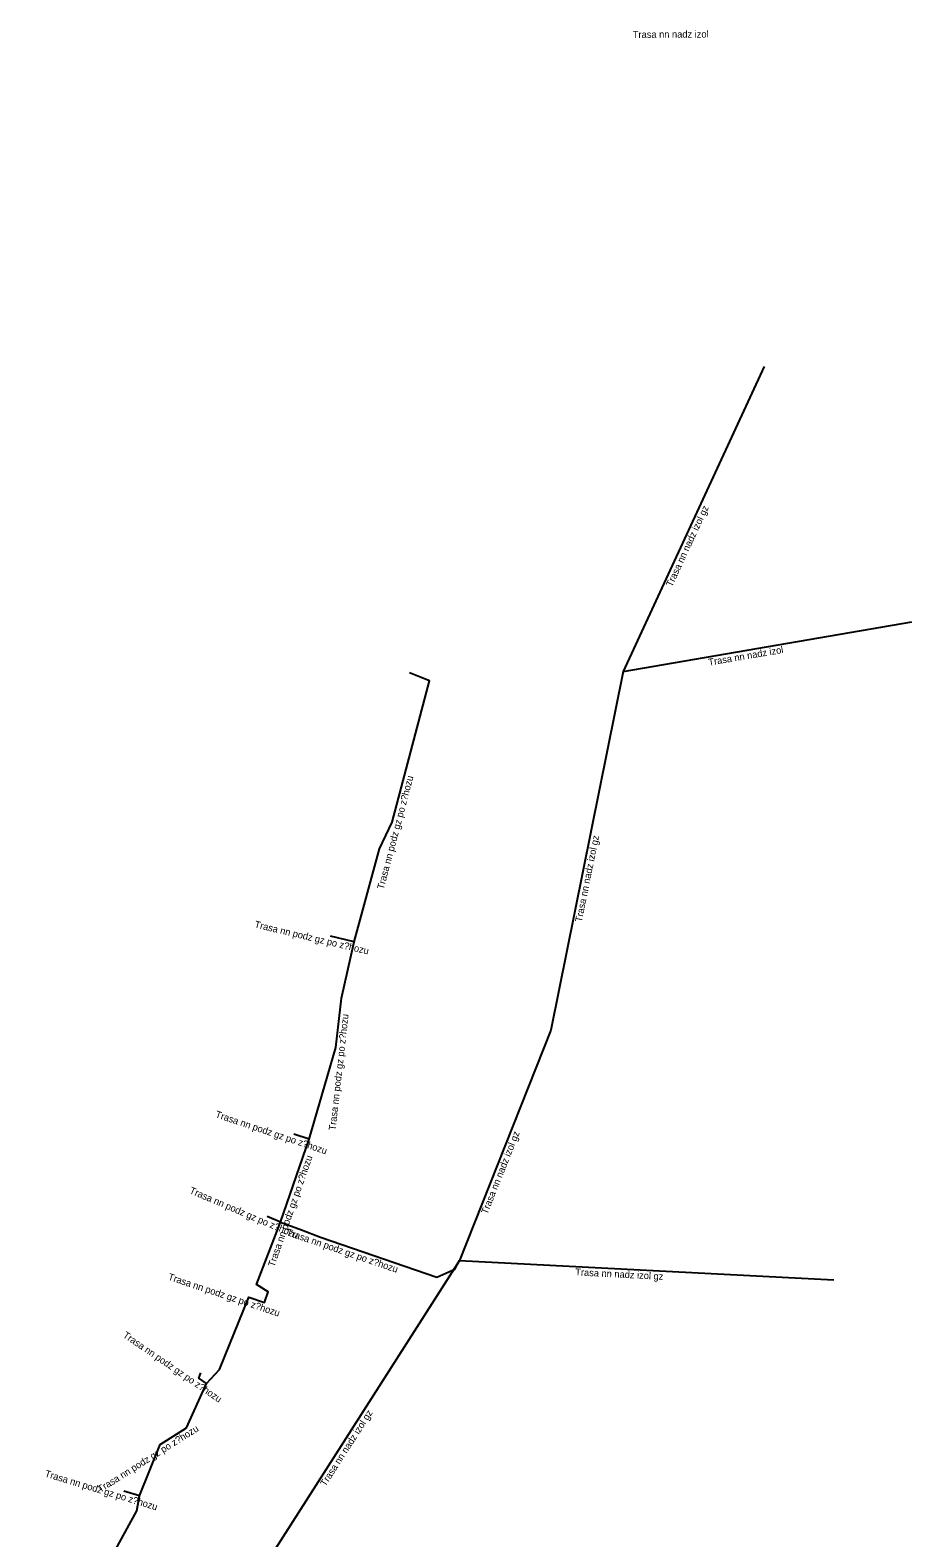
# Model space of a CAD drawing. Extents: x -770668 to -770481, y -1049958 to -1049459.
# Drawn here: x -770567.4 to -770503.8, y -1049855.1 to -1049746.5 of the extents above; entities that cross this region are included whole.
import ezdxf

# ---------------------------------------------------------------- set-up
doc = ezdxf.new("R2010")
doc.units = 0
doc.layers.add('Popiskový text - Ostatní atributy Trasy', color=7, linetype='Continuous')
doc.layers.add('Spojnice NN', color=7, linetype='Continuous')

msp = doc.modelspace()

# ---------------------------------------------------------------- linework, layer by layer
at = {"layer": 'Spojnice NN'}
for points in [[(-770514.47, -1049770.7), (-770524.63, -1049792.67)], [(-770524.63, -1049792.67), (-770503.83, -1049789.09)], [(-770544.02, -1049812.16), (-770542.19, -1049805.45), (-770541.29, -1049803.54), (-770538.6, -1049793.34), (-770540.04, -1049792.78)], [(-770524.63, -1049792.67), (-770529.85, -1049818.52)], [(-770547.27, -1049826.38), (-770545.95, -1049821.84), (-770545.35, -1049819.76), (-770544.95, -1049816.21), (-770544.02, -1049812.16)], [(-770544.02, -1049812.16), (-770545.74, -1049811.75)], [(-770529.85, -1049818.52), (-770536.43, -1049835.1)], [(-770549.34, -1049832.36), (-770547.27, -1049826.38)], [(-770547.27, -1049826.38), (-770548.37, -1049826.01)], [(-770549.34, -1049832.36), (-770550.3, -1049831.95)], [(-770554.67, -1049843.97), (-770553.72, -1049842.97), (-770551.62, -1049837.76), (-770550.48, -1049838.14), (-770550.22, -1049837.36), (-770551.07, -1049836.85), (-770549.34, -1049832.36)], [(-770549.34, -1049832.36), (-770547.83, -1049832.89), (-770546.46, -1049833.44), (-770538.06, -1049836.32), (-770536.77, -1049835.74), (-770536.43, -1049835.1)], [(-770536.43, -1049835.1), (-770551.17, -1049858.17), (-770551.32, -1049858.4)], [(-770536.43, -1049835.1), (-770509.45, -1049836.5)], [(-770559.51, -1049852.07), (-770558.02, -1049848.37), (-770556.1, -1049847.16), (-770554.67, -1049843.97)], [(-770554.67, -1049843.97), (-770555.21, -1049843.6), (-770555.07, -1049843.2)], [(-770567.38, -1049865.01), (-770562.73, -1049858.73), (-770559.69, -1049853.14), (-770559.51, -1049852.07)], [(-770559.51, -1049852.07), (-770560.63, -1049851.73)]]:
    msp.add_lwpolyline(points, dxfattribs=at)

# ---------------------------------------------------------------- texts
at = {"layer": 'Popiskový text - Ostatní atributy Trasy'}
for s, rotation, p in [('Trasa nn nadz izol', 0.3776, (-770523.94, -1049747.03)), ('Trasa nn nadz izol gz', 65.1819, (-770521.12, -1049786.62)), ('Trasa nn nadz izol', 9.7658, (-770518.45, -1049792.26)), ('Trasa nn podz gz po z?hozu', 75.226, (-770541.9, -1049808.41)), ('Trasa nn nadz izol gz', 78.5835, (-770527.62, -1049810.76)), ('Trasa nn podz gz po z?hozu', 346.5925, (-770551.24, -1049811.11)), ('Trasa nn podz gz po z?hozu', 83.5713, (-770545.37, -1049825.76)), ('Trasa nn podz gz po z?hozu', 341.4089, (-770554.07, -1049824.78)), ('Trasa nn nadz izol gz', 68.3537, (-770534.43, -1049831.82)), ('Trasa nn podz gz po z?hozu', 70.9065, (-770549.78, -1049835.61)), ('Trasa nn podz gz po z?hozu', 336.8735, (-770555.94, -1049830.25)), ('Trasa nn podz gz po z?hozu', 341.0754, (-770548.95, -1049833.27)), ('Trasa nn podz gz po z?hozu', 341.5651, (-770557.48, -1049836.49)), ('Trasa nn nadz izol gz', 357.0296, (-770528.1, -1049836.18)), ('Trasa nn podz gz po z?hozu', 325.5816, (-770560.74, -1049840.6)), ('Trasa nn nadz izol gz', 57.4291, (-770546.09, -1049851.43)), ('Trasa nn podz gz po z?hozu', 32.2195, (-770562.32, -1049851.85)), ('Trasa nn podz gz po z?hozu', 343.1132, (-770566.36, -1049850.67))]:
    msp.add_text(s, height=0.5, rotation=rotation, dxfattribs=at).set_placement(p)

doc.saveas('drawing.dxf')
